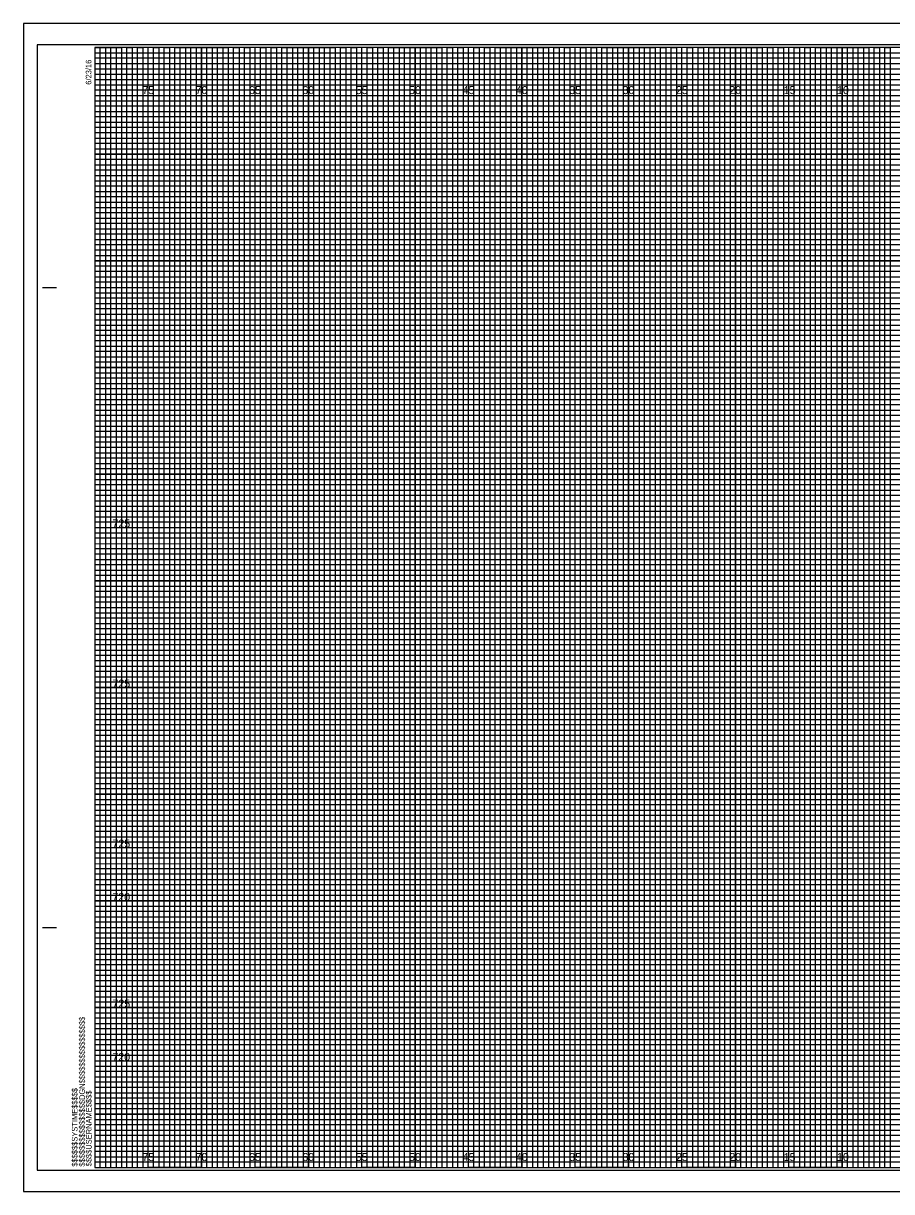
# Model space of a CAD drawing. Extents: x -7 to 162, y -2 to 107.
# Drawn here: x -6.7 to 74.6, y -2.3 to 107.3 of the extents above; entities that cross this region are included whole.
import ezdxf

# ---------------------------------------------------------------- set-up
doc = ezdxf.new("R2010")
doc.units = 0
for name, color, linetype in [('Exist XS Center Line Elevation Label', 7, 'Continuous'), ('Prop CMT Pvmt Course 1', 7, 'Continuous'), ('Prop CMT Pvmt Course 2', 7, 'Continuous'), ('Prop CMT Pvmt Course 3', 7, 'Continuous'), ('Prop CMT Pvmt Surface', 7, 'Continuous'), ('Prop CMT Shld Paved Course 1', 7, 'Continuous'), ('Prop CMT Shld Paved Course 2', 7, 'Continuous'), ('Prop CMT Shld Paved Course 3', 7, 'Continuous'), ('Prop CMT Subgrade Earthwork', 7, 'Continuous'), ('Prop XS SE Text', 7, 'Continuous'), ('Scratch_Level_5', 7, 'Continuous')]:
    doc.layers.add(name, color=color, linetype=linetype)

msp = doc.modelspace()

# ---------------------------------------------------------------- linework, layer by layer
at = {"layer": 'Prop CMT Pvmt Course 1'}
msp.add_lwpolyline([(-6.7, -2.25), (161.65, -2.25), (161.65, 107.25), (-6.7, 107.25)], close=True, dxfattribs=at)
at = {"layer": 'Prop CMT Pvmt Course 2'}
msp.add_lwpolyline([(-5.4, -0.25), (161.2, -0.25), (161.2, 105.25), (-5.4, 105.25)], close=True, dxfattribs=at)
at = {"layer": 'Prop CMT Pvmt Course 3'}
for p, q in [((5, 0), (5, 105)), ((10, 0), (10, 105)), ((15, 0), (15, 105)), ((20, 0), (20, 105)), ((25, 0), (25, 105)), ((30, 0), (30, 105)), ((35, 0), (35, 105)), ((40, 0), (40, 105)), ((45, 0), (45, 105)), ((50, 0), (50, 105)), ((55, 0), (55, 105)), ((60, 0), (60, 105)), ((65, 0), (65, 105)), ((70, 0), (70, 105)), ((0, 100), (160, 100)), ((0, 95), (160, 95)), ((0, 90), (160, 90)), ((0, 85), (160, 85)), ((0, 80), (160, 80)), ((0, 75), (160, 75)), ((0, 70), (160, 70)), ((0, 65), (160, 65)), ((0, 60), (160, 60)), ((0, 55), (160, 55)), ((0, 50), (160, 50)), ((0, 45), (160, 45)), ((0, 40), (160, 40)), ((0, 35), (160, 35)), ((0, 30), (160, 30)), ((0, 25), (160, 25)), ((0, 20), (160, 20)), ((0, 15), (160, 15)), ((0, 10), (160, 10)), ((0, 5), (160, 5))]:
    msp.add_line(p, q, dxfattribs=at)
at = {"layer": 'Prop CMT Pvmt Surface'}
for points in [[(0, 0), (0.5, 0), (0.5, 105), (1, 105), (1, 0)], [(1, 0), (1.5, 0), (1.5, 105), (2, 105), (2, 0)], [(2.5, 0), (3, 0), (3, 105), (3.5, 105), (3.5, 0)], [(3.5, 0), (4, 0), (4, 105), (4.5, 105), (4.5, 0)], [(5, 0), (5.5, 0), (5.5, 105), (6, 105), (6, 0)], [(6, 0), (6.5, 0), (6.5, 105), (7, 105), (7, 0)], [(7.5, 0), (8, 0), (8, 105), (8.5, 105), (8.5, 0)], [(8.5, 0), (9, 0), (9, 105), (9.5, 105), (9.5, 0)], [(10, 0), (10.5, 0), (10.5, 105), (11, 105), (11, 0)], [(11, 0), (11.5, 0), (11.5, 105), (12, 105), (12, 0)], [(12.5, 0), (13, 0), (13, 105), (13.5, 105), (13.5, 0)], [(13.5, 0), (14, 0), (14, 105), (14.5, 105), (14.5, 0)], [(15, 0), (15.5, 0), (15.5, 105), (16, 105), (16, 0)], [(16, 0), (16.5, 0), (16.5, 105), (17, 105), (17, 0)], [(17.5, 0), (18, 0), (18, 105), (18.5, 105), (18.5, 0)], [(18.5, 0), (19, 0), (19, 105), (19.5, 105), (19.5, 0)], [(20, 0), (20.5, 0), (20.5, 105), (21, 105), (21, 0)], [(21, 0), (21.5, 0), (21.5, 105), (22, 105), (22, 0)], [(22.5, 0), (23, 0), (23, 105), (23.5, 105), (23.5, 0)], [(23.5, 0), (24, 0), (24, 105), (24.5, 105), (24.5, 0)], [(25, 0), (25.5, 0), (25.5, 105), (26, 105), (26, 0)], [(26, 0), (26.5, 0), (26.5, 105), (27, 105), (27, 0)], [(27.5, 0), (28, 0), (28, 105), (28.5, 105), (28.5, 0)], [(28.5, 0), (29, 0), (29, 105), (29.5, 105), (29.5, 0)], [(30, 0), (30.5, 0), (30.5, 105), (31, 105), (31, 0)], [(31, 0), (31.5, 0), (31.5, 105), (32, 105), (32, 0)], [(32.5, 0), (33, 0), (33, 105), (33.5, 105), (33.5, 0)], [(33.5, 0), (34, 0), (34, 105), (34.5, 105), (34.5, 0)], [(35, 0), (35.5, 0), (35.5, 105), (36, 105), (36, 0)], [(36, 0), (36.5, 0), (36.5, 105), (37, 105), (37, 0)], [(37.5, 0), (38, 0), (38, 105), (38.5, 105), (38.5, 0)], [(38.5, 0), (39, 0), (39, 105), (39.5, 105), (39.5, 0)], [(40, 0), (40.5, 0), (40.5, 105), (41, 105), (41, 0)], [(41, 0), (41.5, 0), (41.5, 105), (42, 105), (42, 0)], [(42.5, 0), (43, 0), (43, 105), (43.5, 105), (43.5, 0)], [(43.5, 0), (44, 0), (44, 105), (44.5, 105), (44.5, 0)], [(45, 0), (45.5, 0), (45.5, 105), (46, 105), (46, 0)], [(46, 0), (46.5, 0), (46.5, 105), (47, 105), (47, 0)], [(47.5, 0), (48, 0), (48, 105), (48.5, 105), (48.5, 0)], [(48.5, 0), (49, 0), (49, 105), (49.5, 105), (49.5, 0)], [(50, 0), (50.5, 0), (50.5, 105), (51, 105), (51, 0)], [(51, 0), (51.5, 0), (51.5, 105), (52, 105), (52, 0)], [(52.5, 0), (53, 0), (53, 105), (53.5, 105), (53.5, 0)], [(53.5, 0), (54, 0), (54, 105), (54.5, 105), (54.5, 0)], [(55, 0), (55.5, 0), (55.5, 105), (56, 105), (56, 0)], [(56, 0), (56.5, 0), (56.5, 105), (57, 105), (57, 0)], [(57.5, 0), (58, 0), (58, 105), (58.5, 105), (58.5, 0)], [(58.5, 0), (59, 0), (59, 105), (59.5, 105), (59.5, 0)], [(60, 0), (60.5, 0), (60.5, 105), (61, 105), (61, 0)], [(61, 0), (61.5, 0), (61.5, 105), (62, 105), (62, 0)], [(62.5, 0), (63, 0), (63, 105), (63.5, 105), (63.5, 0)], [(63.5, 0), (64, 0), (64, 105), (64.5, 105), (64.5, 0)], [(65, 0), (65.5, 0), (65.5, 105), (66, 105), (66, 0)], [(66, 0), (66.5, 0), (66.5, 105), (67, 105), (67, 0)], [(67.5, 0), (68, 0), (68, 105), (68.5, 105), (68.5, 0)], [(68.5, 0), (69, 0), (69, 105), (69.5, 105), (69.5, 0)], [(70, 0), (70.5, 0), (70.5, 105), (71, 105), (71, 0)], [(71, 0), (71.5, 0), (71.5, 105), (72, 105), (72, 0)], [(72.5, 0), (73, 0), (73, 105), (73.5, 105), (73.5, 0)], [(73.5, 0), (74, 0), (74, 105), (74.5, 105), (74.5, 0)]]:
    msp.add_lwpolyline(points, dxfattribs=at)
at = {"layer": 'Prop CMT Shld Paved Course 1'}
for p, q in [((5, 105), (0, 105)), ((5, 0), (5, 105)), ((15, 105), (10, 105)), ((10, 105), (10, 0)), ((15, 0), (15, 105)), ((25, 105), (20, 105)), ((20, 105), (20, 0)), ((25, 0), (25, 105)), ((35, 105), (30, 105)), ((30, 105), (30, 0)), ((35, 0), (35, 105)), ((45, 105), (40, 105)), ((40, 105), (40, 0)), ((45, 0), (45, 105)), ((55, 105), (50, 105)), ((50, 105), (50, 0)), ((55, 0), (55, 105)), ((65, 105), (60, 105)), ((60, 105), (60, 0)), ((65, 0), (65, 105)), ((75, 105), (70, 105)), ((70, 105), (70, 0)), ((10, 0), (5, 0)), ((20, 0), (15, 0)), ((30, 0), (25, 0)), ((40, 0), (35, 0)), ((50, 0), (45, 0)), ((60, 0), (55, 0)), ((70, 0), (65, 0))]:
    msp.add_line(p, q, dxfattribs=at)
for points in [[(0, 100), (160, 100), (160, 95), (0, 95)], [(0, 90), (160, 90), (160, 85), (0, 85)], [(0, 80), (160, 80), (160, 75), (0, 75)], [(0, 70), (160, 70), (160, 65), (0, 65)], [(0, 60), (160, 60), (160, 55), (0, 55)], [(0, 50), (160, 50), (160, 45), (0, 45)], [(0, 40), (160, 40), (160, 35), (0, 35)], [(0, 30), (160, 30), (160, 25), (0, 25)], [(0, 20), (160, 20), (160, 15), (0, 15)], [(0, 10), (160, 10), (160, 5), (0, 5)]]:
    msp.add_lwpolyline(points, dxfattribs=at)
at = {"layer": 'Prop CMT Shld Paved Course 2'}
for points in [[(0, 105), (2.5, 105), (2.5, 0), (7.5, 0), (7.5, 105), (12.5, 105), (12.5, 0), (17.5, 0), (17.5, 105), (22.5, 105), (22.5, 0), (27.5, 0), (27.5, 105), (32.5, 105), (32.5, 0), (37.5, 0), (37.5, 105), (42.5, 105), (42.5, 0), (47.5, 0), (47.5, 105), (52.5, 105), (52.5, 0), (57.5, 0), (57.5, 105), (62.5, 105), (62.5, 0), (67.5, 0), (67.5, 105), (72.5, 105), (72.5, 0), (77.5, 0)], [(0, 102.5), (137.5, 102.5)], [(0, 92.5), (160, 92.5), (160, 97.5), (0, 97.5)], [(0, 82.5), (160, 82.5), (160, 87.5), (0, 87.5)], [(0, 72.5), (160, 72.5), (160, 77.5), (0, 77.5)], [(0, 62.5), (160, 62.5), (160, 67.5), (0, 67.5)], [(0, 52.5), (160, 52.5), (160, 57.5), (0, 57.5)], [(0, 42.5), (160, 42.5), (160, 47.5), (0, 47.5)], [(0, 32.5), (160, 32.5), (160, 37.5), (0, 37.5)], [(0, 22.5), (160, 22.5), (160, 27.5), (0, 27.5)], [(0, 12.5), (160, 12.5), (160, 17.5), (0, 17.5)], [(0, 2.5), (160, 2.5), (160, 7.5), (0, 7.5)]]:
    msp.add_lwpolyline(points, dxfattribs=at)
at = {"layer": 'Prop CMT Shld Paved Course 3'}
for p, q in [((0, 104.5), (130, 104.5)), ((130, 103.99), (0, 103.99)), ((0, 103.99), (0, 103.5)), ((0, 103.5), (130, 103.5)), ((130, 102.95), (0, 102.95)), ((0, 102.95), (0, 102)), ((0, 102), (160, 102))]:
    msp.add_line(p, q, dxfattribs=at)
for points in [[(0, 101.5), (135, 101.5), (160, 101.5), (160, 101), (0, 101)], [(0, 100.5), (160, 100.5), (160, 99.5), (0, 99.5)], [(0, 99), (160, 99), (160, 98.5), (0, 98.49)], [(0, 98), (160, 98), (160, 97), (0, 97)], [(0, 96.5), (160, 96.5), (160, 96), (0, 96)], [(0, 95.5), (160, 95.5), (160, 94.5), (0, 94.5)], [(0, 94), (160, 94), (160, 93.5), (0, 93.5)], [(0, 93), (160, 93), (160, 92), (0, 92)], [(0, 91.5), (160, 91.5), (160, 91), (0, 91)], [(0, 90.5), (160, 90.5), (160, 89.5), (0, 89.5)], [(0, 89), (160, 89), (160, 88.5), (0, 88.5)], [(0, 88), (160, 88), (160, 86.98), (160, 86.5), (160, 86), (0, 86)], [(0, 87), (160, 87), (160, 86.5), (0, 86.5)], [(0, 85.5), (160, 85.5), (160, 84.5), (0, 84.52)], [(0, 84.52), (160, 84.5), (160, 84), (0, 84)], [(0, 83.5), (160, 83.5), (160, 83), (0, 83)], [(0, 82), (160, 82), (160, 81.5), (0, 81.5)], [(0, 81), (160, 81), (160, 80.5), (0, 80.5)], [(-0.04, 79.45), (160, 79.45), (160, 78.94), (-0.04, 78.94)], [(0, 78.5), (160, 78.5), (160, 78), (0, 78)], [(0, 77), (160, 77), (160, 76.5), (0, 76.5)], [(0, 76), (160, 76), (160, 75.5), (0, 75.5)], [(0, 74.5), (160, 74.5), (160, 74), (0, 74)], [(0, 73.5), (160, 73.5), (160, 73), (0, 73)], [(0, 72), (160, 72), (160, 71.5), (0, 71.5)], [(0, 71), (160, 71), (160, 70.5), (0, 70.5)], [(0, 69.5), (160, 69.5), (160, 68.99), (0, 69)], [(0, 68.5), (160, 68.5), (160, 68), (0, 68)], [(0, 67), (160, 67), (160, 66.5), (0, 66.5)], [(0, 66), (160, 66), (160, 65.5), (0, 65.5)], [(0, 64.5), (160, 64.5), (160, 64), (0, 64)], [(0, 63.5), (160, 63.5), (160, 63), (0, 63)], [(0, 62), (160, 62), (160, 61.5), (0, 61.5)], [(0, 61), (160, 61), (160, 60.5), (0, 60.5)], [(0, 59.5), (160, 59.5), (160, 59), (0, 59)], [(0, 58.5), (160.03, 58.45), (160, 58), (0, 58)], [(0, 57), (160, 57), (160, 56.5), (0, 56.5)], [(0, 56), (160, 56), (160, 55.5), (0, 55.5)], [(0, 54.5), (160, 54.5), (160, 54), (0, 54)], [(0, 53.5), (160, 53.5), (160, 53), (0, 53)], [(0, 52), (160, 52), (160, 51.5), (0, 51.5)], [(0, 51), (160, 51), (160, 50.5), (0, 50.5)], [(0, 49.5), (160, 49.5), (160, 49), (0, 49)], [(0, 48.5), (160, 48.5), (160, 48), (0, 48)], [(0, 47), (160, 47), (160, 46.5), (0, 46.5)], [(0, 46), (160, 46), (160, 45.5), (0, 45.5)], [(0, 44.5), (160, 44.5), (160, 44), (0, 44)], [(0, 43.5), (160, 43.5), (160, 43), (0, 43)], [(0, 42), (160, 42), (160, 41.5), (0, 41.5)], [(0, 41), (160, 41), (160, 40.5), (0, 40.5)], [(0, 39.5), (160, 39.5), (160, 38.99), (0, 39)], [(0, 38.5), (160, 38.5), (160, 38), (0, 38)], [(0, 37), (160, 37), (160, 36.5), (0, 36.5)], [(0, 36), (160, 36), (160, 35.5), (0, 35.5)], [(0, 34.5), (160, 34.5), (160, 34), (0, 34)], [(0, 33.5), (160, 33.5), (160, 33), (0, 33)], [(0, 32), (160, 32), (160, 31.5), (0, 31.5)], [(0, 31), (160, 31), (160, 30.5), (0, 30.5)], [(0, 29.5), (160, 29.5), (160, 29), (0, 29)], [(0, 28.5), (160.03, 28.46), (160, 28), (0, 28)], [(0, 27), (160, 27), (160, 26.5), (0, 26.5)], [(0, 26), (160, 26), (160, 25.5), (0, 25.5)], [(0, 24.5), (160, 24.5), (160, 24), (0, 24)], [(0, 23.5), (160, 23.5), (160, 23), (0, 23)], [(0, 22), (160, 22), (160, 21.5), (0, 21.5)], [(0, 21), (160, 21), (160, 20.5), (0, 20.5)], [(0, 19.5), (160, 19.5), (160, 19), (0, 19)], [(0, 18.5), (160, 18.5), (160, 18), (0, 18)], [(0, 17), (160, 17), (160, 16.5), (0, 16.5)], [(0, 16), (160, 16), (160, 15.5), (0, 15.5)], [(0, 14.5), (160, 14.5), (160, 14), (0, 14)], [(0, 13.5), (160, 13.5), (160, 13), (0, 13)], [(0, 12), (160, 12), (160, 11.5), (0, 11.5)], [(0, 11), (160, 11), (160, 10.5), (0, 10.5)], [(0, 9.5), (160, 9.5), (160, 9), (0, 9)], [(0, 8.5), (160, 8.5), (160, 8), (0, 8)], [(0, 7), (160, 7), (160, 6.5), (0, 6.5)], [(0, 6), (160, 6), (160, 5.5), (0, 5.5)], [(0, 4.5), (160, 4.5), (160, 4), (0, 4)], [(0, 3.5), (160, 3.5), (160, 3), (0, 3)], [(0, 2), (160, 2), (160, 1.5), (0, 1.5)], [(0, 1), (160, 1), (160, 0.5), (0, 0.5)]]:
    msp.add_lwpolyline(points, dxfattribs=at)
at = {"layer": 'Prop CMT Subgrade Earthwork'}
for p, q in [((-4.9, 82.5), (-3.65, 82.5)), ((-4.85, 82.5), (-3.6, 82.5)), ((-4.9, 22.5), (-3.65, 22.5)), ((-4.85, 22.5), (-3.6, 22.5)), ((0, 0), (0, 0)), ((0, 0), (0, 0)), ((0, 0), (0, 0)), ((0, 0), (0, 0)), ((0, 0), (0, 0)), ((0, 0), (0, 0)), ((0, 0), (0, 0))]:
    msp.add_line(p, q, dxfattribs=at)
msp.add_lwpolyline([(160, 105), (0, 105), (0, 0), (160, 0)], close=True, dxfattribs=at)
at = {"layer": 'Prop XS SE Text'}
for p, q in [((161.65, 107.25), (-6.7, 107.25)), ((-6.7, 107.25), (-6.7, -2.25)), ((-6.7, -2.25), (161.65, -2.25))]:
    msp.add_line(p, q, dxfattribs=at)

# ---------------------------------------------------------------- texts
at = {"layer": 'Exist XS Center Line Elevation Label'}
for s, p in [('75', (4.44, 100.62)), ('70', (9.43, 100.62)), ('65', (14.44, 100.62)), ('60', (19.43, 100.62)), ('55', (24.44, 100.62)), ('50', (29.43, 100.62)), ('45', (34.44, 100.62)), ('40', (39.43, 100.62)), ('35', (44.44, 100.62)), ('30', (49.43, 100.62)), ('25', (54.44, 100.62)), ('20', (59.43, 100.62)), ('15', (64.53, 100.62)), ('10', (69.52, 100.62)), ('75', (4.44, 0.62)), ('70', (9.43, 0.62)), ('65', (14.44, 0.62)), ('60', (19.43, 0.62)), ('55', (24.44, 0.62)), ('50', (29.43, 0.62)), ('45', (34.44, 0.62)), ('40', (39.43, 0.62)), ('35', (44.44, 0.62)), ('30', (49.43, 0.62)), ('25', (54.44, 0.62)), ('20', (59.43, 0.62)), ('15', (64.53, 0.62)), ('10', (69.52, 0.62))]:
    msp.add_text(s, height=0.75, dxfattribs=at).set_placement(p)
at = {"layer": 'Prop CMT Subgrade Earthwork'}
for s, p in [('6/23/16', (-0.33, 101.5)), ('$$$$$$$$$$$$$$$$DGN$$$$$$$$$$$$$$$$', (-0.94, 0.09)), ('$$$$$$SYSTIME$$$$$', (-1.63, 0.09)), ('$$$$USERNAME$$$$', (-0.31, 0.12))]:
    msp.add_text(s, height=0.525, rotation=90, dxfattribs=at).set_placement(p)
at = {"layer": 'Scratch_Level_5'}
for s, p in [('725', (1.64, 60)), ('725', (1.64, 45)), ('725', (1.64, 30)), ('720', (1.63, 25)), ('725', (1.64, 15)), ('720', (1.63, 10))]:
    msp.add_text(s, height=0.75, dxfattribs=at).set_placement(p)

doc.saveas('drawing.dxf')
